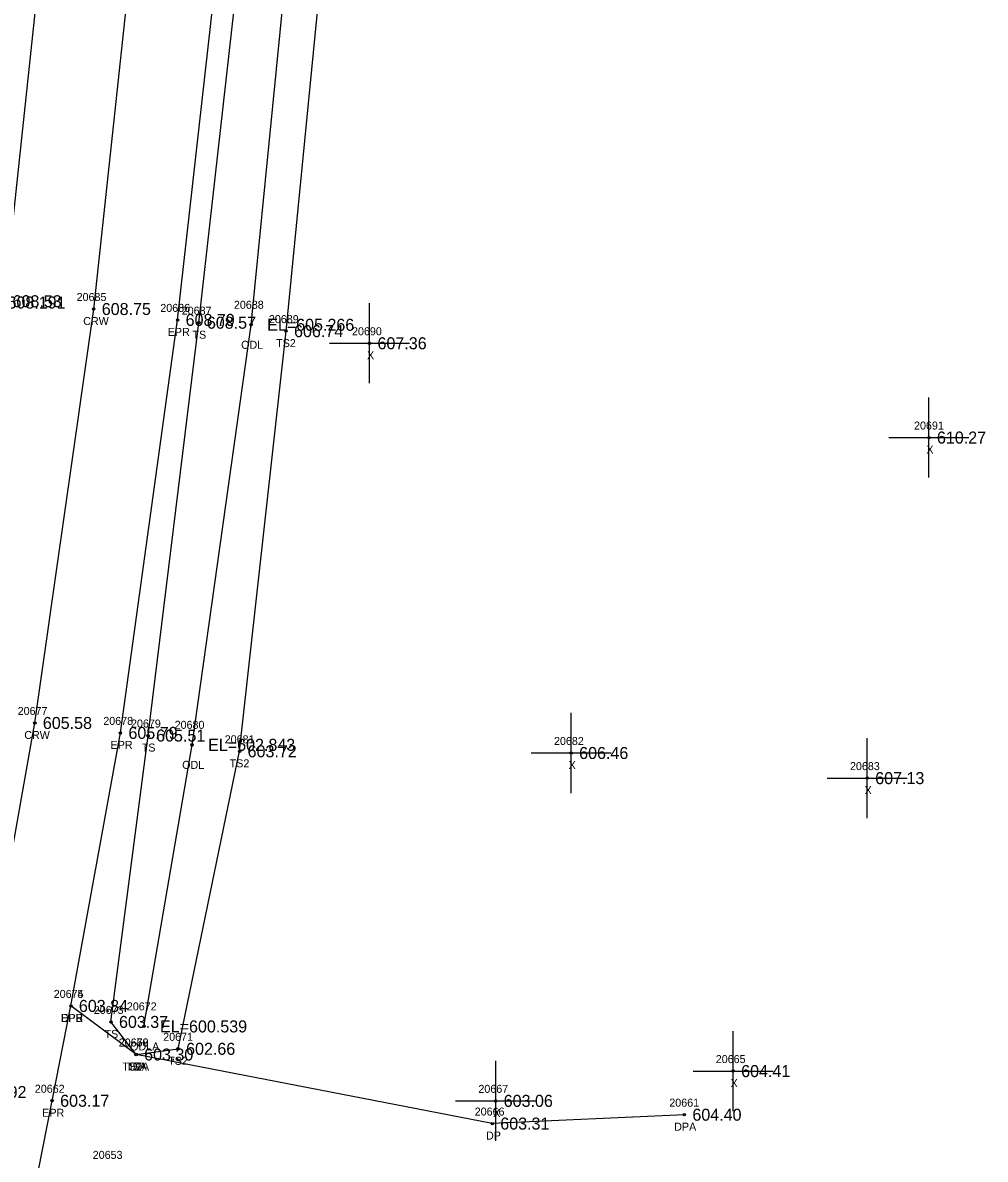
# Model space of a CAD drawing. Extents: x 1695443 to 1696344, y 1087542 to 1090645.
# Drawn here: x 1695817 to 1695937.2, y 1089816.1 to 1089958.1 of the extents above; entities that cross this region are included whole.
import ezdxf

# ---------------------------------------------------------------- set-up
doc = ezdxf.new("R2010")
doc.units = 0
for name, color, linetype in [('RD_DTM_BkLn1', 7, 'Continuous'), ('RD_DTM_BkLn2', 7, 'Continuous'), ('RD_DTM_BkLn_txCode', 7, 'Continuous'), ('RD_EX_Driveway', 7, 'Continuous'), ('RD_EX_Driveway_txCode', 7, 'Continuous'), ('RD_EX_H2O', 7, 'Continuous'), ('RD_EX_H2O_txCode', 7, 'Continuous'), ('RD_EX_Misc', 7, 'Continuous'), ('RD_EX_Misc_txCode', 7, 'Continuous'), ('RD_EX_Road', 7, 'Continuous'), ('RD_EX_Road_txCode', 7, 'Continuous'), ('RD_EX_TX_Driveway_ELEV', 7, 'Continuous'), ('RD_EX_TX_H2O_ELEV', 7, 'Continuous'), ('RD_EX_TX_Misc_ELEV', 7, 'Continuous'), ('RD_EX_TX_Road_ELEV', 7, 'Continuous'), ('RD_HC_Survey_ELEV', 7, 'Continuous'), ('RD_HC_Survey_txCode', 7, 'Continuous'), ('RD_SMD_Locator', 7, 'Continuous')]:
    doc.layers.add(name, color=color, linetype=linetype)

msp = doc.modelspace()

# ---------------------------------------------------------------- linework, layer by layer
at = {"layer": 'RD_DTM_BkLn1'}
msp.add_lwpolyline([(1695813.78, 1089148.1), (1695785.55, 1089189.03), (1695758.89, 1089235.87), (1695740.64, 1089279.02), (1695725.17, 1089334.02), (1695718.27, 1089382.65), (1695717.41, 1089435.13), (1695722.03, 1089482.62), (1695732.64, 1089534.75), (1695759.85, 1089631.43), (1695787.11, 1089727.89), (1695798.89, 1089774.41), (1695810.31, 1089824.5), (1695818.49, 1089870.61), (1695825.85, 1089922.33), (1695831.69, 1089976.57), (1695835.49, 1090019.27), (1695844.06, 1090117.91), (1695852.56, 1090215.73), (1695861.78, 1090313.02), (1695870.8, 1090411.68), (1695879.44, 1090510.15), (1695888.04, 1090606.94)], dxfattribs=at)
at = {"layer": 'RD_DTM_BkLn2'}
for points in [[(1695831.14, 1089829.19), (1695828, 1089833.26), (1695832.64, 1089869.04), (1695838.97, 1089920.62), (1695845.1, 1089974.98), (1695848.98, 1090018.22), (1695852.88, 1090051.95), (1695857.59, 1090054.22), (1695862.49, 1090050.71)], [(1695831.14, 1089829.19), (1695836.38, 1089829.9), (1695844.06, 1089867.07), (1695849.86, 1089919.57), (1695855.22, 1089973.96), (1695858.02, 1090018.57), (1695862.49, 1090050.71)]]:
    msp.add_lwpolyline(points, dxfattribs=at)
at = {"layer": 'RD_EX_Driveway'}
msp.add_lwpolyline([(1695899.6, 1089821.67), (1695875.61, 1089820.56), (1695831.14, 1089829.19), (1695822.99, 1089835.26)], dxfattribs=at)
at = {"layer": 'RD_EX_H2O'}
msp.add_lwpolyline([(1695832.12, 1089832.7), (1695838.13, 1089867.88), (1695845.5, 1089920.36), (1695850.91, 1089975.04), (1695854.21, 1090019.17), (1695857.28, 1090049.4)], dxfattribs=at)
at = {"layer": 'RD_EX_Misc'}
for p, q in [((1695860.28, 1089913.05), (1695860.28, 1089923.05)), ((1695855.28, 1089918.05), (1695865.28, 1089918.05)), ((1695930.14, 1089901.27), (1695930.14, 1089911.27)), ((1695925.14, 1089906.27), (1695935.14, 1089906.27)), ((1695885.46, 1089861.86), (1695885.46, 1089871.86)), ((1695922.43, 1089858.72), (1695922.43, 1089868.72)), ((1695880.46, 1089866.86), (1695890.46, 1089866.86)), ((1695917.43, 1089863.72), (1695927.43, 1089863.72)), ((1695905.69, 1089822.12), (1695905.69, 1089832.12)), ((1695876.04, 1089818.4), (1695876.04, 1089828.4)), ((1695900.69, 1089827.12), (1695910.69, 1089827.12)), ((1695871.04, 1089823.4), (1695881.04, 1089823.4))]:
    msp.add_line(p, q, dxfattribs=at)
at = {"layer": 'RD_EX_Road'}
for points in [[(1695813.78, 1089148.1), (1695805.56, 1089142.08), (1695776.44, 1089183.94), (1695749.27, 1089231.88), (1695730.49, 1089275.72), (1695714.87, 1089332.12), (1695707.87, 1089381.72), (1695706.58, 1089435.34), (1695711.58, 1089484.26), (1695722.15, 1089537.59), (1695749.04, 1089634.88), (1695776.11, 1089730.43), (1695788.13, 1089777.42), (1695798.89, 1089826.76), (1695807.1, 1089870.03), (1695814.71, 1089923.3), (1695820.51, 1089978.16), (1695824.04, 1090019.79), (1695832.76, 1090119.06), (1695841.25, 1090216.76), (1695850.36, 1090314.41), (1695859.24, 1090411.82), (1695868.09, 1090511.63), (1695876.75, 1090608.38)], [(1695728.69, 1089383.6), (1695727.9, 1089434.83), (1695732.68, 1089480.1), (1695743.4, 1089531.84), (1695770.35, 1089628.36), (1695797.63, 1089725.22), (1695809.49, 1089772.37), (1695818.34, 1089811.57), (1695820.65, 1089823.41), (1695822.99, 1089835.26), (1695829.18, 1089869.37), (1695836.32, 1089920.97), (1695842.44, 1089975.46), (1695846.49, 1090018.55), (1695849.32, 1090055.39), (1695850.91, 1090072.92), (1695855.09, 1090117.49), (1695863.53, 1090214.93), (1695872.56, 1090312.44), (1695881.69, 1090410.78), (1695890.45, 1090509.3), (1695899.01, 1090605.4)]]:
    msp.add_lwpolyline(points, dxfattribs=at)
at = {"layer": 'RD_SMD_Locator'}
for centre in [(1695825.85, 1089922.33), (1695836.32, 1089920.97), (1695838.97, 1089920.62), (1695845.5, 1089920.36), (1695849.86, 1089919.57), (1695860.28, 1089918.05), (1695930.14, 1089906.27), (1695818.49, 1089870.61), (1695829.18, 1089869.37), (1695832.64, 1089869.04), (1695838.13, 1089867.88), (1695844.06, 1089867.07), (1695885.46, 1089866.86), (1695922.43, 1089863.72), (1695822.99, 1089835.26), (1695822.99, 1089835.26), (1695828, 1089833.26), (1695832.12, 1089832.7), (1695836.38, 1089829.9), (1695831.14, 1089829.19), (1695831.14, 1089829.19), (1695831.14, 1089829.19), (1695905.69, 1089827.12), (1695820.65, 1089823.41), (1695876.04, 1089823.4), (1695899.6, 1089821.67), (1695875.61, 1089820.56)]:
    msp.add_circle(centre, 0.15, dxfattribs=at)

# ---------------------------------------------------------------- texts
at = {"layer": 'RD_DTM_BkLn_txCode'}
for s, p in [('20687', (1695836.83, 1089921.62)), ('20689', (1695847.72, 1089920.57)), ('TS', (1695838.18, 1089918.62)), ('TS2', (1695848.62, 1089917.57)), ('20679', (1695830.5, 1089870.04)), ('TS', (1695831.84, 1089867.04)), ('20681', (1695842.2, 1089868.07)), ('TS2', (1695842.82, 1089865.07)), ('20673', (1695825.85, 1089834.26)), ('TS', (1695827.2, 1089831.26)), ('20670', (1695828.96, 1089830.19)), ('20669', (1695828.97, 1089830.19)), ('20671', (1695834.52, 1089830.9)), ('TS2A', (1695829.41, 1089827.19)), ('TSA', (1695829.86, 1089827.19)), ('TS2', (1695835.14, 1089827.9))]:
    msp.add_text(s, height=1, dxfattribs=at).set_placement(p)
at = {"layer": 'RD_EX_Driveway_txCode'}
for s, p in [('20674', (1695820.85, 1089836.26)), ('DPB', (1695821.74, 1089833.26)), ('20668', (1695828.97, 1089830.19)), ('DP', (1695830.36, 1089827.19)), ('20666', (1695873.42, 1089821.56)), ('20661', (1695897.72, 1089822.67)), ('DP', (1695874.83, 1089818.56)), ('DPA', (1695898.33, 1089819.67)), ('20653', (1695825.72, 1089816.15))]:
    msp.add_text(s, height=1, dxfattribs=at).set_placement(p)
at = {"layer": 'RD_EX_H2O_txCode'}
for s, p in [('20688', (1695843.35, 1089922.36)), ('ODL', (1695844.25, 1089917.36)), ('20680', (1695835.95, 1089869.88)), ('ODL', (1695836.89, 1089864.88)), ('20672', (1695829.98, 1089834.7)), ('ODLA', (1695830.39, 1089829.7))]:
    msp.add_text(s, height=1, dxfattribs=at).set_placement(p)
at = {"layer": 'RD_EX_Misc_txCode'}
for s, p in [('20690', (1695858.1, 1089919.05)), ('X', (1695859.97, 1089916.05)), ('20691', (1695928.28, 1089907.27)), ('X', (1695929.82, 1089904.27)), ('20682', (1695883.32, 1089867.86)), ('X', (1695885.14, 1089864.86)), ('20683', (1695920.28, 1089864.72)), ('X', (1695922.11, 1089861.72)), ('20665', (1695903.52, 1089828.12)), ('20667', (1695873.88, 1089824.4)), ('X', (1695905.37, 1089825.12)), ('X', (1695875.73, 1089821.4))]:
    msp.add_text(s, height=1, dxfattribs=at).set_placement(p)
at = {"layer": 'RD_EX_Road_txCode'}
for s, p in [('20686', (1695834.16, 1089921.97)), ('EPR', (1695835.09, 1089918.97)), ('20678', (1695827.04, 1089870.37)), ('EPR', (1695827.95, 1089867.37)), ('20675', (1695820.85, 1089836.26)), ('EPR', (1695821.77, 1089833.26)), ('20662', (1695818.49, 1089824.41)), ('EPR', (1695819.42, 1089821.41))]:
    msp.add_text(s, height=1, dxfattribs=at).set_placement(p)
at = {"layer": 'RD_EX_TX_Driveway_ELEV'}
for s, p in [('603.84', (1695823.99, 1089834.51)), ('603.30', (1695832.14, 1089828.44)), ('604.40', (1695900.6, 1089820.92)), ('603.31', (1695876.61, 1089819.81))]:
    msp.add_text(s, height=1.5, dxfattribs=at).set_placement(p)
at = {"layer": 'RD_EX_TX_H2O_ELEV'}
for s, p in [('EL=608.191', (1695811.45, 1089922.39)), ('EL=605.266', (1695847.5, 1089919.61)), ('EL=602.843', (1695840.13, 1089867.13)), ('EL=600.539', (1695834.12, 1089831.95))]:
    msp.add_text(s, height=1.5, dxfattribs=at).set_placement(p)
at = {"layer": 'RD_EX_TX_Misc_ELEV'}
for s, p in [('608.57', (1695839.97, 1089919.87)), ('606.74', (1695850.86, 1089918.82)), ('607.36', (1695861.28, 1089917.3)), ('610.27', (1695931.14, 1089905.52)), ('605.51', (1695833.64, 1089868.29)), ('603.72', (1695845.06, 1089866.32)), ('606.46', (1695886.46, 1089866.11)), ('607.13', (1695923.43, 1089862.97)), ('603.37', (1695829, 1089832.51)), ('603.30', (1695832.14, 1089828.44)), ('603.30', (1695832.14, 1089828.44)), ('602.66', (1695837.38, 1089829.15)), ('604.41', (1695906.69, 1089826.37)), ('603.06', (1695877.04, 1089822.65))]:
    msp.add_text(s, height=1.5, dxfattribs=at).set_placement(p)
at = {"layer": 'RD_EX_TX_Road_ELEV'}
for s, p in [('608.53', (1695815.71, 1089922.55)), ('608.53', (1695815.71, 1089922.55)), ('608.79', (1695837.32, 1089920.22)), ('605.79', (1695830.18, 1089868.62)), ('603.84', (1695823.99, 1089834.51)), ('603.17', (1695821.65, 1089822.66))]:
    msp.add_text(s, height=1.5, dxfattribs=at).set_placement(p)
at = {"layer": 'RD_HC_Survey_ELEV'}
for s, p in [('608.75', (1695826.85, 1089921.58)), ('605.58', (1695819.49, 1089869.86)), ('602.92', (1695811.31, 1089823.75))]:
    msp.add_text(s, height=1.5, dxfattribs=at).set_placement(p)
at = {"layer": 'RD_HC_Survey_txCode'}
for s, p in [('20685', (1695823.71, 1089923.33)), ('CRW', (1695824.53, 1089920.33)), ('20677', (1695816.35, 1089871.61)), ('CRW', (1695817.17, 1089868.61))]:
    msp.add_text(s, height=1, dxfattribs=at).set_placement(p)

doc.saveas('drawing.dxf')
